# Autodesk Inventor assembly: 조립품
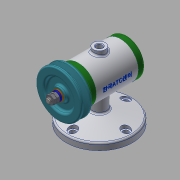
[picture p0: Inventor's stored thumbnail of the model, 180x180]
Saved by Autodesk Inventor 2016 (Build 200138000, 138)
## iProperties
Created: 2018-12
Part Number: 조립품
Material: 일반
Document SubType Name: Assembly
Designer: 605-11
Author: 605-11
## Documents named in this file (14)
- C:\Users\605-11\Desktop\481207V1004\조립품.iam
- C:\Users\605-11\Desktop\481207V1004\본체.ipt
- C:\Users\605-11\Desktop\481207V1004\베어링 15 x 32 x 9.ipt
- C:\Users\605-11\Desktop\481207V1004\축.ipt
- C:\Users\605-11\Desktop\481207V1004\뒤커버.ipt
- C:\Users\605-11\Desktop\481207V1004\볼트 M4 x 12.ipt
- C:\Users\605-11\Desktop\481207V1004\앞커버.ipt
- C:\Users\605-11\Desktop\481207V1004\오일 실 15 25 7.ipt
- C:\Users\605-11\Desktop\481207V1004\키 3 x 3 x 12.ipt
- C:\Users\605-11\Desktop\481207V1004\V벨트풀리.ipt
- C:\Users\605-11\Desktop\481207V1004\와셔 8x17.ipt
- C:\Users\605-11\Desktop\481207V1004\스프링와셔 8.ipt
- C:\Users\605-11\Desktop\481207V1004\너트 M8.ipt
- 너트 M8.ipt
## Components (1 placed, 1 different names)
1. V벨트풀리:1
